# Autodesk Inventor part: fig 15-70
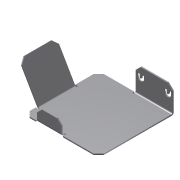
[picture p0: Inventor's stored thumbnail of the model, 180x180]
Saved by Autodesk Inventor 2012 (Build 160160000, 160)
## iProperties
Shininess: 77.0
Angle Display Precision: 2
Document Length Units: 11269
Document Angle Units: 11279
Document Time Units: 11290
Document Mass Units: 11283
Document Length Units Precision: 3
Document Angle Units Precision: 2
Created: 2002-04
Part Number: fig 15-70
Document SubType Name: Sheet Metal
Density: 1 g/cm^3
Sheet Metal Rule: Default
Material: Default
Density: 0.0
Volumn: 0.0
Area: 0.0
PropertySet Name: Model Information
Control State: 0
Master: False
Checked Out: False
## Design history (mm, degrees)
node "Face1"
  sketch "Sketch1"
    geometry: L1 (12.647, 25.882)-(12.647, -14.118); L2 (12.647, -14.118)-(-17.353, -14.118); L3 (-17.353, -14.118)-(-17.353, 15.882); L4 (-17.353, 15.882)-(-2.353, 15.882); L5 (-2.353, 15.882)-(-2.353, 25.882); L6 (-2.353, 25.882)-(12.647, 25.882); 1 further point
    constraints: 12 end point, 4 parallel, 1 perpendicular
    dimensions: "d5" = 30 distance of L2.end L3.end; "d6" = 10 distance of L4.end L5.end; "d7" = 15 distance of L3.end L4.end; "d25" = 15 distance of L5.end L1.start
sketch "Sketch3"
  geometry: L1 (10, -15)-(10, 0)
  constraints: 2 end point
feature "Fold3" sketch "Sketch3" dims "d26" = 0.5 (= BendRadius), "d27" = 90 deg, "d28" = 0.5 (= BendRadius), "d96" = 0.5 (= BendReliefWidth), "d97" = 0.25 (= BendReliefDepth), "d98" = 1 (= MinimumRemnant), "SeamGap" = 0.01, "Thickness" = 0.5
node "Flange2"
sketch "Sketch6"
  geometry: L1 (-6.914, 3.413)-(-5.843, 3.413); L2 (-5.843, 0.624)-(-6.914, 0.624); L3 (-6.914, 2.432)-(-5.843, 2.432); L4 (-5.843, 1.605)-(-6.914, 1.605); L5 (-6.914, 0.624)-(-6.914, 1.605); L6 (-6.914, 2.432)-(-6.914, 3.413); L7 (-6.914, 12.568)-(-6.914, 11.587); L8 (-6.914, 14.376)-(-6.914, 13.395); L9 (-6.914, 11.587)-(-5.843, 11.587); L10 (-5.843, 14.376)-(-6.914, 14.376); L11 (-6.914, 12.568)-(-5.843, 12.568); L12 (-5.843, 13.395)-(-6.914, 13.395); A1 r 1.394 centre (-5.843, 2.018) between (-5.843, 0.624) and (-5.843, 3.413); A2 r 0.413 centre (-5.843, 2.018) between (-5.843, 1.605) and (-5.843, 2.432); A3 r 1.394 centre (-5.843, 12.982) between (-5.843, 11.587) and (-5.843, 14.376); A4 r 0.413 centre (-5.843, 12.982) between (-5.843, 12.568) and (-5.843, 13.395)
  constraints: 24 end point, 8 point on circle, 4 centre point, 3 equal length, 1 perpendicular
cut "Cut1" sketch "Sketch6" dims "d49" = 0.5 (= Thickness), "d50" = 0
node "Flange3"
feature "Corner Chamfer3" dims "d107" = 2, "d108" = 6, angle "d109" = 45 deg
feature "Corner Chamfer4" dims "d110" = 2, "d111" = 6, angle "d112" = 45 deg
feature "Corner Chamfer5" dims "d113" = 2, "d114" = 6, angle "d115" = 45 deg
feature "Corner Chamfer6" dims "d116" = 2, "d117" = 6, angle "d118" = 45 deg
body "Solid1"
face "Plate1" dims "Thickness" = 0.5
sketch "Sketch5"
  geometry: L1 (20, 0)-(5, 0); L2 (5, 0)-(5, 15); L3 (5, 15)-(20, 15); L4 (20, 15)-(20, 0)
  constraints: 8 end point
face "Plate6" dims "d35" = 10, "d36" = 5, "d38" = 15, "d39" = 60 deg, "d40" = 0.5 (= BendRadius), "Thickness" = 0.5, "MinimumRemnant" = 1 (= 2 x Thickness), "BendReliefWidth" = 0.5 (= Thickness)
bend "Bend5" dims "d38" = 15, "d39" = 60 deg, "d40" = 0.5 (= BendRadius), "d99" = 0.5 (= BendReliefWidth), "d100" = 0.25 (= BendReliefDepth), "d101" = 1 (= MinimumRemnant), "SeamGap" = 0.01, "Thickness" = 0.5, "MinimumRemnant" = 1 (= 2 x Thickness), "BendReliefWidth" = 0.5 (= Thickness), "TransitionRadius" = 0.5 (= BendRadius)
sketch "Sketch7"
  geometry: L1 (25, 0)-(15, 0); L2 (15, 0)-(15, 5); L3 (15, 5)-(25, 5); L4 (25, 5)-(25, 0)
  constraints: 8 end point
face "Plate7" dims "d57" = 5, "d58" = 10, "d60" = 5, "d61" = 90 deg, "d62" = 0.5 (= BendRadius), "Thickness" = 0.5, "MinimumRemnant" = 1 (= 2 x Thickness), "BendReliefWidth" = 0.5 (= Thickness)
bend "Bend7" dims "d59" = 0.5 (= BendRadius), "d60" = 5, "d61" = 90 deg, "d62" = 0.5 (= BendRadius), "d102" = 0.5 (= BendReliefWidth), "d103" = 0.25 (= BendReliefDepth), "d104" = 1 (= MinimumRemnant), "SeamGap" = 0.01, "Thickness" = 0.5, "MinimumRemnant" = 1 (= 2 x Thickness), "BendReliefWidth" = 0.5 (= Thickness)
other parameters: "BendRadius" = 0.5 (= Thickness), "BendReliefDepth" = 0.25 (= 0.5 x Thickness), "CornerReliefSize" = 2 (= 4 x Thickness), "d0" = 0.5 (= BendRadius), "d13" = 0.5 (= BendRadius), "d31" = 0.5 (= BendRadius), "d37" = 0.5 (= BendRadius), "JacobiRadiusSize" = 0.5 (= Thickness), "GapSize" = 0.5 (= Thickness)
